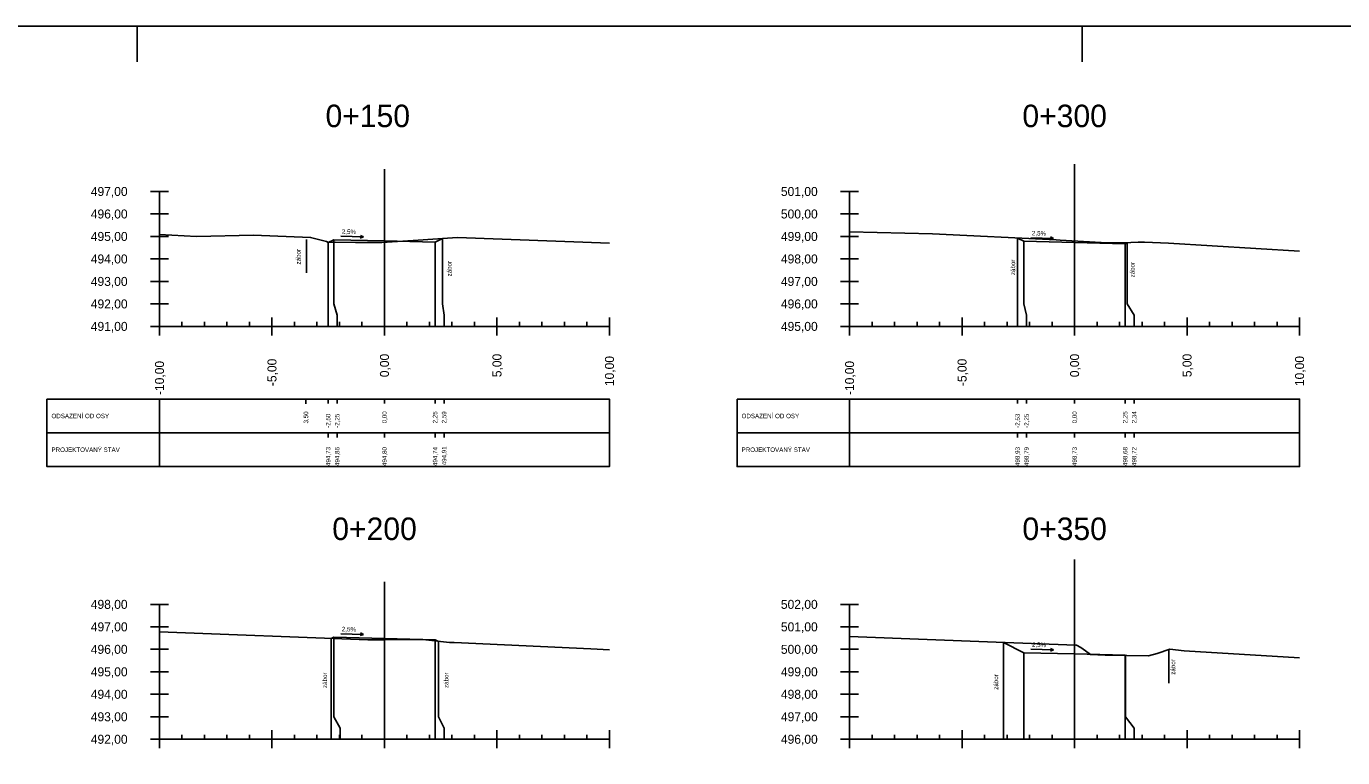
# Model space of a CAD drawing. Extents: x -631407 to -631215, y -1089700 to -1088598.
# Drawn here: x -631373.8 to -631315.3, y -1088630.2 to -1088597.7 of the extents above; entities that cross this region are included whole.
import ezdxf

# ---------------------------------------------------------------- set-up
doc = ezdxf.new("R2010")
doc.units = 0
for name, color, linetype in [('08_LEGENDA_HV', 7, 'Continuous'), ('59', 7, 'Continuous'), ('DTM-Breaklines', 7, 'Continuous'), ('NIVELETA_VYSKY', 7, 'Continuous'), ('REZ_BODY', 7, 'Continuous'), ('REZ_ODSTUPY', 7, 'Continuous'), ('REZ_POPIS', 7, 'Continuous'), ('REZ_RAMY', 7, 'Continuous'), ('REZ_STANICENI', 7, 'Continuous'), ('REZ_SVISLE', 7, 'Continuous'), ('REZ_TENKA', 7, 'Continuous'), ('REZ_TLUSTA', 7, 'Continuous'), ('TABULKA_POPIS', 7, 'Continuous'), ('TEREN', 7, 'Continuous'), ('zábor', 7, 'Continuous')]:
    doc.layers.add(name, color=color, linetype=linetype)

msp = doc.modelspace()

# ---------------------------------------------------------------- linework, layer by layer
at = {"layer": '08_LEGENDA_HV'}
msp.add_lwpolyline([(-631242.839, -1088657.106), (-631242.839, -1088597.706), (-631407.014, -1088597.706), (-631407.014, -1088657.106)], close=True, dxfattribs=at)
at = {"layer": '59'}
for p, q in [((-631368.243, -1088605.052), (-631367.443, -1088605.052)), ((-631367.843, -1088605.052), (-631367.843, -1088611.052)), ((-631337.571, -1088605.052), (-631336.771, -1088605.052)), ((-631337.171, -1088605.052), (-631337.171, -1088611.052)), ((-631368.243, -1088606.052), (-631367.443, -1088606.052)), ((-631337.571, -1088606.052), (-631336.771, -1088606.052)), ((-631368.243, -1088607.052), (-631367.443, -1088607.052)), ((-631337.571, -1088607.052), (-631336.771, -1088607.052)), ((-631368.243, -1088608.052), (-631367.443, -1088608.052)), ((-631337.571, -1088608.052), (-631336.771, -1088608.052)), ((-631368.243, -1088609.052), (-631367.443, -1088609.052)), ((-631337.571, -1088609.052), (-631336.771, -1088609.052)), ((-631368.243, -1088610.052), (-631367.443, -1088610.052)), ((-631337.571, -1088610.052), (-631336.771, -1088610.052)), ((-631368.243, -1088611.052), (-631367.443, -1088611.052)), ((-631337.571, -1088611.052), (-631336.771, -1088611.052)), ((-631368.243, -1088623.414), (-631367.443, -1088623.414)), ((-631367.843, -1088623.414), (-631367.843, -1088629.414)), ((-631337.571, -1088623.414), (-631336.771, -1088623.414)), ((-631337.171, -1088623.414), (-631337.171, -1088629.414)), ((-631368.243, -1088624.414), (-631367.443, -1088624.414)), ((-631337.571, -1088624.414), (-631336.771, -1088624.414)), ((-631368.243, -1088625.414), (-631367.443, -1088625.414)), ((-631337.571, -1088625.414), (-631336.771, -1088625.414)), ((-631368.243, -1088626.414), (-631367.443, -1088626.414)), ((-631337.571, -1088626.414), (-631336.771, -1088626.414)), ((-631368.243, -1088627.414), (-631367.443, -1088627.414)), ((-631337.571, -1088627.414), (-631336.771, -1088627.414)), ((-631368.243, -1088628.414), (-631367.443, -1088628.414)), ((-631337.571, -1088628.414), (-631336.771, -1088628.414)), ((-631368.243, -1088629.414), (-631367.443, -1088629.414)), ((-631337.571, -1088629.414), (-631336.771, -1088629.414))]:
    msp.add_line(p, q, dxfattribs=at)
at = {"layer": 'DTM-Breaklines'}
for p, q in [((-631368.839, -1088599.286), (-631368.839, -1088597.706)), ((-631326.839, -1088599.286), (-631326.839, -1088597.706))]:
    msp.add_line(p, q, dxfattribs=at)
at = {"layer": 'REZ_RAMY'}
for p, q in [((-631372.843, -1088614.286), (-631372.843, -1088617.286)), ((-631367.843, -1088614.286), (-631367.843, -1088617.286)), ((-631361.333, -1088614.491), (-631361.333, -1088614.291)), ((-631360.345, -1088614.486), (-631360.345, -1088614.286)), ((-631359.945, -1088614.486), (-631359.945, -1088614.286)), ((-631357.843, -1088614.486), (-631357.843, -1088614.286)), ((-631355.593, -1088614.486), (-631355.593, -1088614.286)), ((-631355.193, -1088614.486), (-631355.193, -1088614.286)), ((-631342.171, -1088614.286), (-631342.171, -1088617.286)), ((-631337.171, -1088614.286), (-631337.171, -1088617.286)), ((-631329.705, -1088614.486), (-631329.705, -1088614.286)), ((-631329.305, -1088614.486), (-631329.305, -1088614.286)), ((-631327.171, -1088614.486), (-631327.171, -1088614.286)), ((-631324.921, -1088614.486), (-631324.921, -1088614.286)), ((-631324.521, -1088614.486), (-631324.521, -1088614.286)), ((-631372.843, -1088615.786), (-631347.843, -1088615.786)), ((-631360.345, -1088615.986), (-631360.345, -1088615.786)), ((-631359.945, -1088615.986), (-631359.945, -1088615.786)), ((-631357.843, -1088615.986), (-631357.843, -1088615.786)), ((-631355.593, -1088615.986), (-631355.593, -1088615.786)), ((-631355.193, -1088615.986), (-631355.193, -1088615.786)), ((-631342.171, -1088615.786), (-631317.171, -1088615.786)), ((-631329.705, -1088615.986), (-631329.705, -1088615.786)), ((-631329.305, -1088615.986), (-631329.305, -1088615.786)), ((-631327.171, -1088615.986), (-631327.171, -1088615.786)), ((-631324.921, -1088615.986), (-631324.921, -1088615.786)), ((-631324.521, -1088615.986), (-631324.521, -1088615.786))]:
    msp.add_line(p, q, dxfattribs=at)
for points in [[(-631372.843, -1088614.286), (-631372.843, -1088617.286), (-631347.843, -1088617.286), (-631347.843, -1088614.286)], [(-631342.171, -1088614.286), (-631342.171, -1088617.286), (-631317.171, -1088617.286), (-631317.171, -1088614.286)]]:
    msp.add_lwpolyline(points, close=True, dxfattribs=at)
at = {"layer": 'REZ_SVISLE'}
for points in [[(-631360.345, -1088607.321), (-631360.345, -1088610.052), (-631360.345, -1088610.552), (-631360.345, -1088611.052)], [(-631360.093, -1088607.196), (-631360.093, -1088610.052), (-631359.945, -1088610.552), (-631359.945, -1088611.052)], [(-631357.843, -1088607.252), (-631357.843, -1088610.052), (-631357.843, -1088610.552), (-631357.843, -1088611.052)], [(-631355.593, -1088607.308), (-631355.593, -1088610.052), (-631355.593, -1088610.552), (-631355.593, -1088611.052)], [(-631355.257, -1088607.14), (-631355.257, -1088610.052), (-631355.193, -1088610.552), (-631355.193, -1088611.052)], [(-631329.705, -1088607.122), (-631329.705, -1088610.052), (-631329.705, -1088610.552), (-631329.705, -1088611.052)], [(-631329.421, -1088607.265), (-631329.421, -1088610.052), (-631329.305, -1088610.552), (-631329.305, -1088611.052)], [(-631327.171, -1088607.321), (-631327.171, -1088610.052), (-631327.171, -1088610.552), (-631327.171, -1088611.052)], [(-631324.921, -1088607.377), (-631324.921, -1088610.052), (-631324.921, -1088610.552), (-631324.921, -1088611.052)], [(-631324.828, -1088607.331), (-631324.828, -1088610.052), (-631324.521, -1088610.552), (-631324.521, -1088611.052)], [(-631360.209, -1088624.93), (-631360.209, -1088628.414), (-631360.209, -1088628.914), (-631360.209, -1088629.414)], [(-631360.093, -1088624.873), (-631360.093, -1088628.414), (-631359.809, -1088628.914), (-631359.809, -1088629.414)], [(-631357.843, -1088624.929), (-631357.843, -1088628.414), (-631357.843, -1088628.914), (-631357.843, -1088629.414)], [(-631355.593, -1088624.985), (-631355.593, -1088628.414), (-631355.593, -1088628.914), (-631355.593, -1088629.414)], [(-631355.445, -1088625.059), (-631355.445, -1088628.414), (-631355.193, -1088628.914), (-631355.193, -1088629.414)], [(-631330.33, -1088625.109), (-631330.33, -1088628.414), (-631330.33, -1088628.914), (-631330.33, -1088629.414)], [(-631329.421, -1088625.564), (-631329.421, -1088628.414), (-631329.421, -1088628.914), (-631329.421, -1088629.414)], [(-631327.171, -1088625.62), (-631327.171, -1088628.414), (-631327.171, -1088628.914), (-631327.171, -1088629.414)], [(-631324.921, -1088625.676), (-631324.921, -1088628.414), (-631324.921, -1088628.914), (-631324.921, -1088629.414)], [(-631324.909, -1088625.682), (-631324.909, -1088628.414), (-631324.521, -1088628.914), (-631324.521, -1088629.414)]]:
    msp.add_lwpolyline(points, dxfattribs=at)
at = {"layer": 'REZ_TENKA'}
for p, q in [((-631366.843, -1088611.052), (-631366.843, -1088610.852)), ((-631365.843, -1088611.052), (-631365.843, -1088610.852)), ((-631364.843, -1088611.052), (-631364.843, -1088610.852)), ((-631363.843, -1088611.052), (-631363.843, -1088610.852)), ((-631361.843, -1088611.052), (-631361.843, -1088610.852)), ((-631360.843, -1088611.052), (-631360.843, -1088610.852)), ((-631359.843, -1088611.052), (-631359.843, -1088610.852)), ((-631358.843, -1088611.052), (-631358.843, -1088610.852)), ((-631356.843, -1088611.052), (-631356.843, -1088610.852)), ((-631355.843, -1088611.052), (-631355.843, -1088610.852)), ((-631354.843, -1088611.052), (-631354.843, -1088610.852)), ((-631353.843, -1088611.052), (-631353.843, -1088610.852)), ((-631351.843, -1088611.052), (-631351.843, -1088610.852)), ((-631350.843, -1088611.052), (-631350.843, -1088610.852)), ((-631349.843, -1088611.052), (-631349.843, -1088610.852)), ((-631348.843, -1088611.052), (-631348.843, -1088610.852)), ((-631336.171, -1088611.052), (-631336.171, -1088610.852)), ((-631335.171, -1088611.052), (-631335.171, -1088610.852)), ((-631334.171, -1088611.052), (-631334.171, -1088610.852)), ((-631333.171, -1088611.052), (-631333.171, -1088610.852)), ((-631331.171, -1088611.052), (-631331.171, -1088610.852)), ((-631330.171, -1088611.052), (-631330.171, -1088610.852)), ((-631329.171, -1088611.052), (-631329.171, -1088610.852)), ((-631328.171, -1088611.052), (-631328.171, -1088610.852)), ((-631326.171, -1088611.052), (-631326.171, -1088610.852)), ((-631325.171, -1088611.052), (-631325.171, -1088610.852)), ((-631324.171, -1088611.052), (-631324.171, -1088610.852)), ((-631323.171, -1088611.052), (-631323.171, -1088610.852)), ((-631321.171, -1088611.052), (-631321.171, -1088610.852)), ((-631320.171, -1088611.052), (-631320.171, -1088610.852)), ((-631319.171, -1088611.052), (-631319.171, -1088610.852)), ((-631318.171, -1088611.052), (-631318.171, -1088610.852)), ((-631366.843, -1088629.414), (-631366.843, -1088629.214)), ((-631365.843, -1088629.414), (-631365.843, -1088629.214)), ((-631364.843, -1088629.414), (-631364.843, -1088629.214)), ((-631363.843, -1088629.414), (-631363.843, -1088629.214)), ((-631361.843, -1088629.414), (-631361.843, -1088629.214)), ((-631360.843, -1088629.414), (-631360.843, -1088629.214)), ((-631359.843, -1088629.414), (-631359.843, -1088629.214)), ((-631358.843, -1088629.414), (-631358.843, -1088629.214)), ((-631356.843, -1088629.414), (-631356.843, -1088629.214)), ((-631355.843, -1088629.414), (-631355.843, -1088629.214)), ((-631354.843, -1088629.414), (-631354.843, -1088629.214)), ((-631353.843, -1088629.414), (-631353.843, -1088629.214)), ((-631351.843, -1088629.414), (-631351.843, -1088629.214)), ((-631350.843, -1088629.414), (-631350.843, -1088629.214)), ((-631349.843, -1088629.414), (-631349.843, -1088629.214)), ((-631348.843, -1088629.414), (-631348.843, -1088629.214)), ((-631336.171, -1088629.414), (-631336.171, -1088629.214)), ((-631335.171, -1088629.414), (-631335.171, -1088629.214)), ((-631334.171, -1088629.414), (-631334.171, -1088629.214)), ((-631333.171, -1088629.414), (-631333.171, -1088629.214)), ((-631331.171, -1088629.414), (-631331.171, -1088629.214)), ((-631330.171, -1088629.414), (-631330.171, -1088629.214)), ((-631329.171, -1088629.414), (-631329.171, -1088629.214)), ((-631328.171, -1088629.414), (-631328.171, -1088629.214)), ((-631326.171, -1088629.414), (-631326.171, -1088629.214)), ((-631325.171, -1088629.414), (-631325.171, -1088629.214)), ((-631324.171, -1088629.414), (-631324.171, -1088629.214)), ((-631323.171, -1088629.414), (-631323.171, -1088629.214)), ((-631321.171, -1088629.414), (-631321.171, -1088629.214)), ((-631320.171, -1088629.414), (-631320.171, -1088629.214)), ((-631319.171, -1088629.414), (-631319.171, -1088629.214)), ((-631318.171, -1088629.414), (-631318.171, -1088629.214))]:
    msp.add_line(p, q, dxfattribs=at)
at = {"layer": 'REZ_TLUSTA'}
for p, q in [((-631327.171, -1088603.832), (-631327.171, -1088611.052)), ((-631357.843, -1088604.052), (-631357.843, -1088611.052)), ((-631367.843, -1088611.452), (-631367.843, -1088610.652)), ((-631362.843, -1088611.452), (-631362.843, -1088610.652)), ((-631357.843, -1088611.452), (-631357.843, -1088610.652)), ((-631352.843, -1088611.452), (-631352.843, -1088610.652)), ((-631347.843, -1088611.452), (-631347.843, -1088610.652)), ((-631337.171, -1088611.452), (-631337.171, -1088610.652)), ((-631332.171, -1088611.452), (-631332.171, -1088610.652)), ((-631327.171, -1088611.452), (-631327.171, -1088610.652)), ((-631322.171, -1088611.452), (-631322.171, -1088610.652)), ((-631317.171, -1088611.452), (-631317.171, -1088610.652)), ((-631367.843, -1088611.052), (-631347.843, -1088611.052)), ((-631337.171, -1088611.052), (-631317.171, -1088611.052)), ((-631327.171, -1088621.414), (-631327.171, -1088629.414)), ((-631357.843, -1088622.414), (-631357.843, -1088629.414)), ((-631367.843, -1088629.814), (-631367.843, -1088629.014)), ((-631362.843, -1088629.814), (-631362.843, -1088629.014)), ((-631357.843, -1088629.814), (-631357.843, -1088629.014)), ((-631352.843, -1088629.814), (-631352.843, -1088629.014)), ((-631347.843, -1088629.814), (-631347.843, -1088629.014)), ((-631337.171, -1088629.814), (-631337.171, -1088629.014)), ((-631332.171, -1088629.814), (-631332.171, -1088629.014)), ((-631327.171, -1088629.814), (-631327.171, -1088629.014)), ((-631322.171, -1088629.814), (-631322.171, -1088629.014)), ((-631317.171, -1088629.814), (-631317.171, -1088629.014)), ((-631367.843, -1088629.414), (-631347.843, -1088629.414)), ((-631337.171, -1088629.414), (-631317.171, -1088629.414))]:
    msp.add_line(p, q, dxfattribs=at)
at = {"layer": 'TEREN'}
for points in [[(-631337.171, -1088606.852), (-631333.492, -1088606.941), (-631327.995, -1088607.204), (-631327.817, -1088607.223), (-631325.985, -1088607.316), (-631324.989, -1088607.337), (-631324.347, -1088607.312), (-631324.065, -1088607.31), (-631322.994, -1088607.348), (-631317.171, -1088607.7)], [(-631367.843, -1088606.961), (-631366.198, -1088607.061), (-631363.666, -1088607), (-631361.126, -1088607.092), (-631360.419, -1088607.272), (-631360.351, -1088607.322), (-631360.024, -1088607.311), (-631359.136, -1088607.317), (-631357.958, -1088607.319), (-631356.569, -1088607.227), (-631354.604, -1088607.097), (-631347.843, -1088607.347)], [(-631360.345, -1088607.321), (-631360.093, -1088607.196), (-631357.843, -1088607.252), (-631355.593, -1088607.308), (-631355.257, -1088607.14)], [(-631329.705, -1088607.122), (-631329.421, -1088607.265), (-631327.171, -1088607.321), (-631324.921, -1088607.377), (-631324.828, -1088607.331)], [(-631367.843, -1088624.629), (-631358.584, -1088624.995), (-631357.831, -1088624.999), (-631356.139, -1088624.982), (-631354.957, -1088625.113), (-631354.745, -1088625.109), (-631348.671, -1088625.394), (-631347.843, -1088625.442)], [(-631360.209, -1088624.93), (-631360.093, -1088624.873), (-631357.843, -1088624.929), (-631355.593, -1088624.985), (-631355.445, -1088625.059)], [(-631337.171, -1088624.836), (-631330.654, -1088625.097), (-631327.12, -1088625.224), (-631327.082, -1088625.227), (-631327.021, -1088625.256), (-631326.845, -1088625.36), (-631326.462, -1088625.649), (-631325.813, -1088625.668), (-631323.891, -1088625.697), (-631323.499, -1088625.594), (-631322.943, -1088625.413), (-631322.302, -1088625.48), (-631317.171, -1088625.799)], [(-631330.33, -1088625.109), (-631329.421, -1088625.564), (-631327.171, -1088625.62), (-631324.921, -1088625.676), (-631324.909, -1088625.682)]]:
    msp.add_lwpolyline(points, dxfattribs=at)
at = {"layer": 'zábor'}
for p, q in [((-631361.309, -1088607.189), (-631361.309, -1088608.669)), ((-631358.776, -1088607.071), (-631359.784, -1088607.045)), ((-631358.776, -1088607.071), (-631358.916, -1088607.128)), ((-631358.776, -1088607.071), (-631358.913, -1088607.006)), ((-631328.104, -1088607.14), (-631329.112, -1088607.115)), ((-631328.104, -1088607.14), (-631328.243, -1088607.198)), ((-631328.104, -1088607.14), (-631328.24, -1088607.076)), ((-631358.776, -1088624.748), (-631359.784, -1088624.723)), ((-631358.776, -1088624.748), (-631358.916, -1088624.806)), ((-631358.776, -1088624.748), (-631358.913, -1088624.684)), ((-631328.105, -1088625.439), (-631329.113, -1088625.414)), ((-631328.105, -1088625.439), (-631328.244, -1088625.497)), ((-631328.105, -1088625.439), (-631328.241, -1088625.375)), ((-631322.974, -1088625.405), (-631322.974, -1088626.926))]:
    msp.add_line(p, q, dxfattribs=at)

# ---------------------------------------------------------------- texts
at = {"layer": 'NIVELETA_VYSKY'}
for s, p in [('494,73', (-631360.245, -1088617.262)), ('494,86', (-631359.845, -1088617.262)), ('494,80', (-631357.743, -1088617.262)), ('494,74', (-631355.493, -1088617.262)), ('494,91', (-631355.093, -1088617.229)), ('498,93', (-631329.605, -1088617.262)), ('498,79', (-631329.205, -1088617.262)), ('498,73', (-631327.071, -1088617.262)), ('498,68', (-631324.821, -1088617.262)), ('498,72', (-631324.421, -1088617.262))]:
    msp.add_text(s, height=0.2, rotation=90, dxfattribs=at).set_placement(p)
at = {"layer": 'REZ_BODY'}
for s, p in [('3,50', (-631361.233, -1088615.37)), ('-2,50', (-631360.245, -1088615.563)), ('-2,25', (-631359.845, -1088615.563)), ('0,00', (-631357.743, -1088615.365)), ('2,25', (-631355.493, -1088615.365)), ('2,59', (-631355.093, -1088615.365)), ('-2,53', (-631329.605, -1088615.563)), ('-2,25', (-631329.205, -1088615.563)), ('0,00', (-631327.071, -1088615.365)), ('2,25', (-631324.821, -1088615.365)), ('2,34', (-631324.421, -1088615.365))]:
    msp.add_text(s, height=0.2, rotation=90, dxfattribs=at).set_placement(p)
at = {"layer": 'REZ_ODSTUPY'}
for s, p in [('-10,00', (-631367.643, -1088614.104)), ('-5,00', (-631362.643, -1088613.707)), ('0,00', (-631357.643, -1088613.311)), ('5,00', (-631352.643, -1088613.311)), ('10,00', (-631347.643, -1088613.707)), ('-10,00', (-631336.971, -1088614.104)), ('-5,00', (-631331.971, -1088613.707)), ('0,00', (-631326.971, -1088613.311)), ('5,00', (-631321.971, -1088613.311)), ('10,00', (-631316.971, -1088613.707))]:
    msp.add_text(s, height=0.4, rotation=90, dxfattribs=at).set_placement(p)
at = {"layer": 'REZ_POPIS'}
for s, p in [('497,00', (-631370.895, -1088605.252)), ('501,00', (-631340.223, -1088605.252)), ('496,00', (-631370.895, -1088606.252)), ('500,00', (-631340.223, -1088606.252)), ('495,00', (-631370.895, -1088607.252)), ('499,00', (-631340.223, -1088607.252)), ('494,00', (-631370.895, -1088608.252)), ('498,00', (-631340.223, -1088608.252)), ('493,00', (-631370.895, -1088609.252)), ('497,00', (-631340.223, -1088609.252)), ('492,00', (-631370.895, -1088610.252)), ('496,00', (-631340.223, -1088610.252)), ('491,00', (-631370.895, -1088611.252)), ('495,00', (-631340.223, -1088611.252)), ('498,00', (-631370.895, -1088623.614)), ('502,00', (-631340.223, -1088623.614)), ('497,00', (-631370.895, -1088624.614)), ('501,00', (-631340.223, -1088624.614)), ('496,00', (-631370.895, -1088625.614)), ('500,00', (-631340.223, -1088625.614)), ('495,00', (-631370.895, -1088626.614)), ('499,00', (-631340.223, -1088626.614)), ('494,00', (-631370.895, -1088627.614)), ('498,00', (-631340.223, -1088627.614)), ('493,00', (-631370.895, -1088628.614)), ('497,00', (-631340.223, -1088628.614)), ('492,00', (-631370.895, -1088629.614)), ('496,00', (-631340.223, -1088629.614))]:
    msp.add_text(s, height=0.4, dxfattribs=at).set_placement(p)
at = {"layer": 'REZ_STANICENI'}
for s, p in [('0+150', (-631360.462, -1088602.191)), ('0+300', (-631329.49, -1088602.191)), ('0+200', (-631360.162, -1088620.553)), ('0+350', (-631329.49, -1088620.553))]:
    msp.add_text(s, height=1, dxfattribs=at).set_placement(p)
at = {"layer": 'TABULKA_POPIS'}
for s, p in [('ODSAZENÍ OD OSY', (-631372.643, -1088615.136)), ('ODSAZENÍ OD OSY', (-631341.971, -1088615.136)), ('PROJEKTOVANÝ STAV', (-631372.643, -1088616.636)), ('PROJEKTOVANÝ STAV', (-631341.971, -1088616.636))]:
    msp.add_text(s, height=0.2, dxfattribs=at).set_placement(p)
at = {"layer": 'zábor'}
for s, rotation, p in [('2,5%', 358.5679, (-631359.74, -1088606.933)), ('2,5%', 358.5679, (-631329.068, -1088607.003)), ('zábor', 90, (-631361.572, -1088608.297)), ('zábor', 90, (-631354.859, -1088608.829)), ('zábor', 90, (-631329.811, -1088608.772)), ('zábor', 90, (-631324.501, -1088608.873)), ('2,5%', 358.5679, (-631359.74, -1088624.611)), ('2,5%', 358.5679, (-631329.068, -1088625.302)), ('zábor', 90, (-631322.696, -1088626.543)), ('zábor', 90, (-631360.396, -1088627.133)), ('zábor', 90, (-631355.001, -1088627.133)), ('zábor', 90, (-631330.566, -1088627.212))]:
    msp.add_text(s, height=0.2, rotation=rotation, dxfattribs=at).set_placement(p)

doc.saveas('drawing.dxf')
